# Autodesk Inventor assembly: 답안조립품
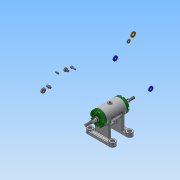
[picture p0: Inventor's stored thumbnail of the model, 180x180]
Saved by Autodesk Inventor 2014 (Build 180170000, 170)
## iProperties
Created: 2015-11
Part Number: 답안조립품
Document SubType Name: Assembly
Designer: 103-08
Author: 103-08
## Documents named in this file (16)
- C:\Users\103-08\Desktop\451110V1027\답안조립품.iam
- C:\Users\103-08\Desktop\451110V1027\본체.ipt
- C:\Users\103-08\Desktop\451110V1027\V벨트풀리.ipt
- C:\Users\103-08\Desktop\451110V1027\너트 M 8.ipt
- C:\Users\103-08\Desktop\451110V1027\니플 M 6 x 0.75.ipt
- C:\Users\103-08\Desktop\451110V1027\베어링 15 x 32 x 9.ipt
- C:\Users\103-08\Desktop\451110V1027\볼트 M 6 x 8.ipt
- C:\Users\103-08\Desktop\451110V1027\볼트 M4 x 12.ipt
- C:\Users\103-08\Desktop\451110V1027\스퍼기어.ipt
- C:\Users\103-08\Desktop\451110V1027\스프링와셔 8.ipt
- C:\Users\103-08\Desktop\451110V1027\오일 실 15 25 7.ipt
- C:\Users\103-08\Desktop\451110V1027\와셔 6x11.5.ipt
- C:\Users\103-08\Desktop\451110V1027\와셔 8x17.ipt
- C:\Users\103-08\Desktop\451110V1027\축.ipt
- C:\Users\103-08\Desktop\451110V1027\커버.ipt
- C:\Users\103-08\Desktop\451110V1027\키 3 x 3 x 12.ipt
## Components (4 placed, 3 different names)
1. V벨트풀리:1
2. KS B 2023 6002 - 15 x 32 x 9:1
3. ISO 4762 M4 x 12:1
4. KS B 2023 6002 - 15 x 32 x 9:2
